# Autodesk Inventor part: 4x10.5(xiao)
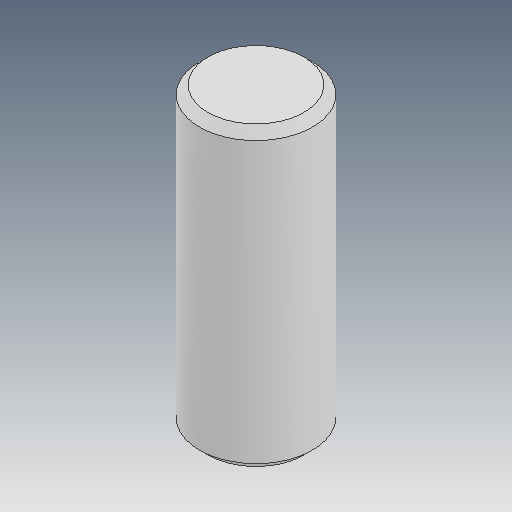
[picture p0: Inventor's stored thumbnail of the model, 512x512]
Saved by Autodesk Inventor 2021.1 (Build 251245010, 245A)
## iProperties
Created: 2021-05
Part Number: 4x10.5(xiao)
Material: Ogólny
Document SubType Name: Modeling
Designer: user
Density: 1 g/cm^3
Appearance: Domyślna
Author: user
Revision Number: ÈÎºÎ
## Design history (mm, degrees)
feature "µ¹½Ç1"
node "Bryła1"
